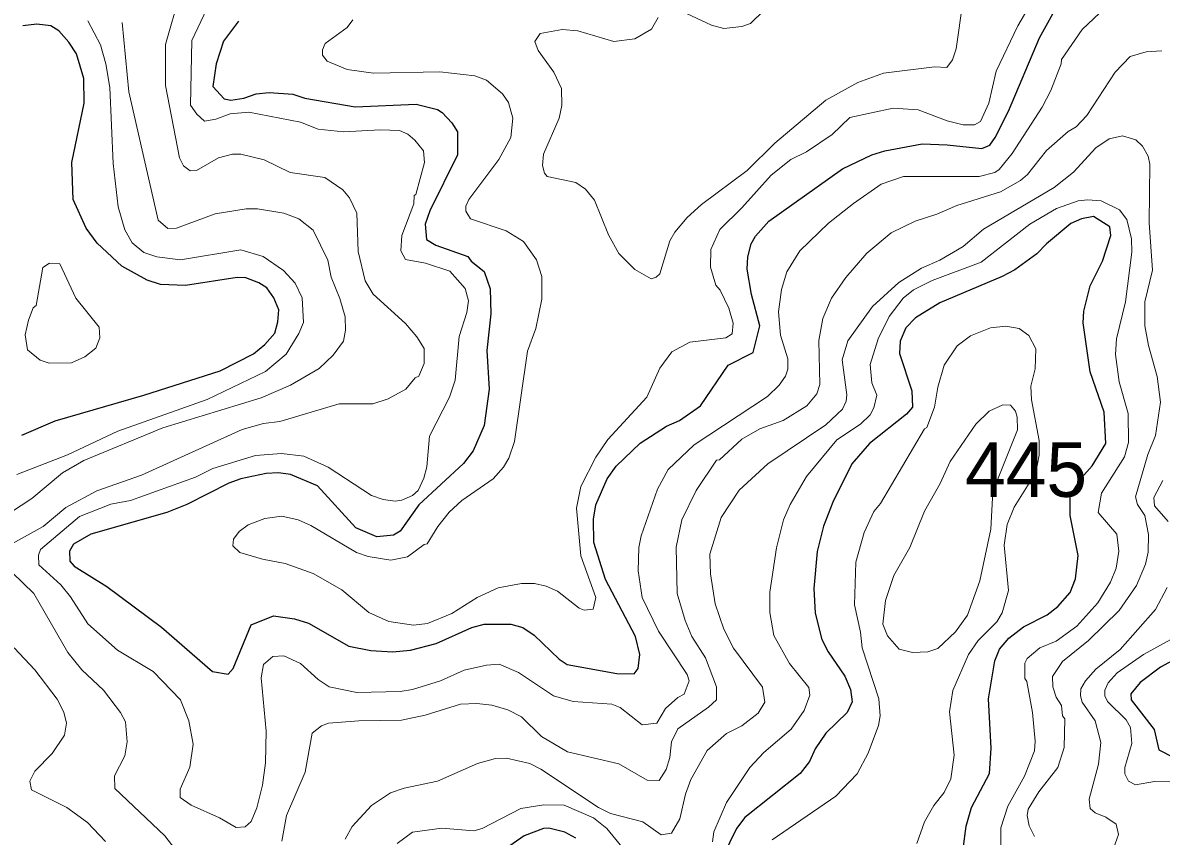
# Model space of a CAD drawing. Extents: x 673.3 to 698.5, y 6984.3 to 7012.3.
# Drawn here: x 691.793 to 693.46, y 6985.799 to 6986.991 of the extents above; entities that cross this region are included whole.
import ezdxf

# ---------------------------------------------------------------- set-up
doc = ezdxf.new("R2010")
doc.units = 0
doc.header["$LTSCALE"] = 0.032
doc.layers.add('1', color=7, linetype='Continuous', lineweight=25)
doc.layers.add('2', color=7, linetype='Continuous', lineweight=13)
doc.layers.add('21', color=7, linetype='Continuous')

msp = doc.modelspace()

# ---------------------------------------------------------------- linework, layer by layer
at = {"layer": '1'}
for points in [[(692.0041, 6986.2732), (691.8929, 6986.2414), (691.8675, 6986.2269), (691.8613, 6986.2167), (691.8618, 6986.202), (691.8684, 6986.1948), (691.9159, 6986.165), (691.9961, 6986.1051), (692.0708, 6986.0402), (692.0938, 6986.0366), (692.1013, 6986.0447), (692.1273, 6986.1088), (692.1603, 6986.122), (692.1909, 6986.1177), (692.2113, 6986.1114), (692.2706, 6986.0777), (692.3028, 6986.0709), (692.3343, 6986.0693), (692.3609, 6986.0718), (692.3983, 6986.0812), (692.4507, 6986.1049), (692.4688, 6986.1095), (692.5077, 6986.1098), (692.5253, 6986.105), (692.5417, 6986.0937), (692.5785, 6986.0586), (692.59, 6986.0505), (692.6627, 6986.0373), (692.6882, 6986.0369), (692.6942, 6986.0447), (692.6965, 6986.0652), (692.6903, 6986.0918), (692.6465, 6986.1751), (692.6291, 6986.2292), (692.6288, 6986.2633), (692.6323, 6986.2846), (692.6488, 6986.3227), (692.6622, 6986.3409), (692.6972, 6986.3747), (692.7355, 6986.3996), (692.7547, 6986.4081), (692.7856, 6986.4294), (692.8258, 6986.4889), (692.8628, 6986.5076), (692.8725, 6986.5469), (692.8603, 6986.5927), (692.8539, 6986.6299), (692.8546, 6986.6478), (692.8598, 6986.6666), (692.8659, 6986.678), (692.8853, 6986.6999), (692.9934, 6986.7768), (693.0364, 6986.797), (693.0553, 6986.8029), (693.11, 6986.8134), (693.1465, 6986.812), (693.1972, 6986.8063), (693.209, 6986.8113), (693.217, 6986.8225), (693.2363, 6986.8612), (693.2821, 6986.9687), (693.3119, 6987.0221)], [(692.1091, 6986.9927), (692.0868, 6986.9636), (692.0762, 6986.9302), (692.0713, 6986.8974), (692.0881, 6986.8789), (692.0978, 6986.8771), (692.1165, 6986.8802), (692.1348, 6986.8867), (692.154, 6986.8884), (692.1885, 6986.8859), (692.2061, 6986.8803), (692.2797, 6986.8672), (692.3692, 6986.8713), (692.4002, 6986.8635), (692.4073, 6986.8593), (692.4215, 6986.8442), (692.4295, 6986.831), (692.4294, 6986.7969), (692.389, 6986.7152), (692.3824, 6986.6958), (692.3843, 6986.6732), (692.3979, 6986.6648), (692.4447, 6986.6482), (692.4495, 6986.6413), (692.4685, 6986.6261), (692.4776, 6986.6009), (692.4785, 6986.5642), (692.4728, 6986.5105), (692.4759, 6986.454), (692.4687, 6986.4009), (692.4527, 6986.3638), (692.4382, 6986.345), (692.3731, 6986.2847), (692.3458, 6986.2461), (692.336, 6986.24), (692.3115, 6986.2378), (692.2805, 6986.2508), (692.2247, 6986.3124), (692.1852, 6986.3289), (692.1676, 6986.3313), (692.1494, 6986.3305), (692.1122, 6986.3225), (692.0947, 6986.3161), (692.0331, 6986.2848), (692.0041, 6986.2732)], [(691.7916, 6986.3866), (691.8402, 6986.4074), (691.9705, 6986.445), (692.0823, 6986.4809), (692.131, 6986.5057), (692.1475, 6986.5192), (692.1619, 6986.5361), (692.1666, 6986.5523), (692.168, 6986.5702), (692.1607, 6986.5878), (692.1503, 6986.6023), (692.1387, 6986.6098), (692.1197, 6986.6172), (692.1072, 6986.6173), (692.0313, 6986.6059), (691.9949, 6986.6074), (691.9754, 6986.6137), (691.9383, 6986.6339), (691.9021, 6986.6675), (691.8859, 6986.6895), (691.8668, 6986.7318), (691.865, 6986.7861), (691.8831, 6986.8726), (691.8822, 6986.9087), (691.8716, 6986.9449), (691.8604, 6986.9623), (691.8456, 6986.9787), (691.8342, 6986.9861), (691.8134, 6986.9886), (691.7929, 6986.9862)], [(693.1699, 6985.7808), (693.1746, 6985.8138), (693.1821, 6985.841), (693.2089, 6985.8909), (693.2113, 6985.928), (693.2073, 6986.0002), (693.2165, 6986.056), (693.2234, 6986.0729), (693.2372, 6986.0892), (693.2586, 6986.1057), (693.2933, 6986.1236), (693.3088, 6986.1357), (693.3269, 6986.1563), (693.3344, 6986.1761), (693.3383, 6986.2103), (693.3269, 6986.2689), (693.327, 6986.2979), (693.3428, 6986.3234), (693.3592, 6986.3418), (693.3792, 6986.3743), (693.3766, 6986.4201), (693.3562, 6986.4792), (693.3458, 6986.5511), (693.3468, 6986.5681), (693.3561, 6986.6051), (693.3741, 6986.6413), (693.3864, 6986.6791), (693.3849, 6986.6916), (693.3612, 6986.7066), (693.3435, 6986.7036), (693.3276, 6986.6964), (693.2919, 6986.6668), (693.2778, 6986.652), (693.2458, 6986.6288), (693.2273, 6986.6187), (693.1361, 6986.5804), (693.1004, 6986.5582), (693.086, 6986.5439), (693.0778, 6986.5243), (693.077, 6986.5061), (693.0948, 6986.4513), (693.0957, 6986.4277), (693.0873, 6986.4174), (693.0327, 6986.3743), (693.0073, 6986.3446), (692.9792, 6986.2882), (692.9657, 6986.253), (692.9564, 6986.2162), (692.9516, 6986.1619), (692.9532, 6986.1256)], [(692.9532, 6986.1256), (692.9633, 6986.0871), (692.9723, 6986.0693), (692.9967, 6986.0334), (693.0053, 6986.0142), (693.0074, 6985.996), (693.0002, 6985.9801), (692.9691, 6985.9499), (692.9534, 6985.9269), (692.945, 6985.9088), (692.9313, 6985.8911), (692.8502, 6985.8266), (692.8381, 6985.8106), (692.8179, 6985.7683)], [(693.5629, 6986.1032), (693.4592, 6986.0465), (693.4293, 6986.0241), (693.4158, 6986.0077), (693.4159, 6985.9989), (693.45, 6985.9556), (693.4567, 6985.9257), (693.4785, 6985.9145)], [(692.6027, 6985.7965), (692.5867, 6985.8052), (692.5632, 6985.8109), (692.5554, 6985.8106), (692.5272, 6985.7995), (692.4901, 6985.7737)]]:
    msp.add_lwpolyline(points, dxfattribs=at)
at = {"layer": '2'}
for points in [[(692.0231, 6987.0323), (692.0022, 6986.9587), (692.0021, 6986.8989), (692.0226, 6986.7925), (692.0284, 6986.7808), (692.0382, 6986.7736), (692.0476, 6986.7743), (692.0796, 6986.7926), (692.1003, 6986.7979), (692.1125, 6986.7979), (692.1464, 6986.7897), (692.1846, 6986.7713), (692.2351, 6986.7638), (692.2615, 6986.746), (692.2713, 6986.7343), (692.2821, 6986.7116), (692.284, 6986.6553), (692.2943, 6986.6126), (692.3061, 6986.5932), (692.3535, 6986.55), (692.3702, 6986.5307), (692.3806, 6986.5134), (692.381, 6986.4915), (692.373, 6986.4727), (692.3677, 6986.4705), (692.354, 6986.4538), (692.3283, 6986.4395), (692.3054, 6986.4323), (692.2561, 6986.4323), (692.1692, 6986.4063), (692.1455, 6986.4037), (692.1141, 6986.395), (691.967, 6986.3279), (691.9016, 6986.3051), (691.8563, 6986.2808), (691.8229, 6986.2529), (691.7781, 6986.2279)], [(692.6104, 6986.2098), (692.6038, 6986.2794), (692.6104, 6986.3112), (692.632, 6986.3544), (692.6499, 6986.3802), (692.7068, 6986.4424), (692.7258, 6986.4849), (692.7434, 6986.5084), (692.77, 6986.5227), (692.8224, 6986.5293), (692.8316, 6986.5349), (692.8334, 6986.5504), (692.8271, 6986.5727), (692.8142, 6986.5988), (692.808, 6986.6063), (692.7999, 6986.6328), (692.8005, 6986.6584), (692.8138, 6986.6877), (692.8462, 6986.7195), (692.8891, 6986.7672), (692.9179, 6986.7904), (692.9407, 6986.8016), (692.9784, 6986.827), (693.0039, 6986.8518), (693.0676, 6986.8656), (693.1044, 6986.863), (693.1465, 6986.847), (693.17, 6986.8412), (693.1866, 6986.8411), (693.1954, 6986.8458), (693.2079, 6986.8729), (693.2183, 6986.9199), (693.2501, 6986.9862), (693.2731, 6987.0258)], [(692.7651, 6987.0039), (692.8017, 6986.9869), (692.8195, 6986.9821), (692.8461, 6986.9851), (692.8588, 6986.9896), (692.8975, 6987.0282)], [(692.282, 6986.0097), (692.2419, 6986.0181), (692.2258, 6986.0285), (692.1998, 6986.052), (692.1754, 6986.0634), (692.1592, 6986.0625), (692.1456, 6986.0508), (692.1421, 6986.0311), (692.1493, 6985.9532), (692.1485, 6985.9064), (692.1443, 6985.874), (692.1357, 6985.8409), (692.1273, 6985.8208), (692.1185, 6985.8128), (692.1057, 6985.8117), (692.0813, 6985.8259), (692.0395, 6985.8448), (692.0233, 6985.8557), (692.0233, 6985.8681), (692.0377, 6985.9001), (692.0427, 6985.9338), (692.0363, 6985.9683), (692.0239, 6985.9991), (691.9839, 6986.0406), (691.9317, 6986.0717), (691.8881, 6986.1104), (691.8629, 6986.1495), (691.8485, 6986.1671), (691.8163, 6986.1964), (691.8161, 6986.2107), (691.819, 6986.2191), (691.8763, 6986.2676), (691.922, 6986.2854), (691.951, 6986.2907), (692.0458, 6986.3252), (692.0712, 6986.3378), (692.1337, 6986.3566), (692.1718, 6986.3599), (692.2047, 6986.3557), (692.2404, 6986.3396), (692.3035, 6986.2983), (692.3207, 6986.2922), (692.3381, 6986.2899), (692.3483, 6986.2915), (692.3638, 6986.2984), (692.3718, 6986.3054), (692.3804, 6986.3234), (692.3847, 6986.3401), (692.3888, 6986.3852), (692.4177, 6986.442), (692.4262, 6986.4671), (692.432, 6986.5312), (692.4433, 6986.566), (692.4459, 6986.5832), (692.4408, 6986.6012), (692.4184, 6986.6266), (692.3826, 6986.6383), (692.3534, 6986.644), (692.3468, 6986.6566), (692.3481, 6986.6791), (692.3656, 6986.7254), (692.366, 6986.7375), (692.3686, 6986.7392), (692.3813, 6986.786), (692.3797, 6986.8029), (692.3671, 6986.8188), (692.357, 6986.8273), (692.3448, 6986.8329), (692.3162, 6986.8339), (692.2627, 6986.8306), (692.2255, 6986.8348), (692.1999, 6986.8452), (692.1239, 6986.8598), (692.0967, 6986.8573), (692.0756, 6986.8492), (692.0592, 6986.8464), (692.0477, 6986.8565), (692.0387, 6986.8697), (692.0404, 6986.9645), (692.067, 6987.0201)], [(693.3873, 6987.0211), (693.3442, 6986.9806), (693.3141, 6986.9367), (693.3138, 6986.9305), (693.2985, 6986.8911), (693.2856, 6986.8667), (693.2419, 6986.7991), (693.2229, 6986.7754), (693.2165, 6986.7711), (693.1937, 6986.7655), (693.0829, 6986.7655), (693.0501, 6986.754), (693.0093, 6986.7259), (692.973, 6986.697), (692.9307, 6986.6566), (692.9118, 6986.6259), (692.904, 6986.6), (692.8995, 6986.5673), (692.9026, 6986.5328), (692.9132, 6986.4983), (692.9132, 6986.4831), (692.9099, 6986.473), (692.9009, 6986.4599), (692.8835, 6986.443), (692.776, 6986.3725), (692.7381, 6986.3362), (692.7225, 6986.3074), (692.6986, 6986.2391), (692.6951, 6986.222), (692.6941, 6986.1876), (692.6999, 6986.149), (692.7242, 6986.0995), (692.7657, 6986.036), (692.7689, 6986.0265), (692.7615, 6986.0071), (692.7524, 6986.0022), (692.7343, 6985.9862), (692.7213, 6985.9647), (692.7, 6985.9625), (692.6676, 6985.9875), (692.6557, 6985.9926), (692.5989, 6985.9966), (692.5702, 6986.0045), (692.5189, 6986.0391), (692.4904, 6986.0511), (692.4722, 6986.0496), (692.4396, 6986.0423), (692.4048, 6986.0266), (692.3639, 6986.0142), (692.3458, 6986.0113), (692.282, 6986.0097)], [(693.1698, 6987.0214), (693.16, 6986.9525), (693.1543, 6986.9365), (693.146, 6986.9252), (693.128, 6986.9258), (693.0536, 6986.9169), (693.0159, 6986.903), (692.9691, 6986.8773), (692.8943, 6986.814), (692.8536, 6986.7741), (692.7871, 6986.7244), (692.7658, 6986.7051), (692.7477, 6986.6839), (692.7405, 6986.6714), (692.7258, 6986.623), (692.7205, 6986.6178), (692.7132, 6986.6156), (692.6891, 6986.629), (692.6658, 6986.6528), (692.6508, 6986.6797), (692.6301, 6986.7307), (692.6169, 6986.7466), (692.6029, 6986.7564), (692.5608, 6986.7655), (692.5569, 6986.7703), (692.5542, 6986.7815), (692.5556, 6986.7979), (692.5787, 6986.8507), (692.5826, 6986.8694), (692.5818, 6986.8941), (692.5706, 6986.9183), (692.5478, 6986.95), (692.5429, 6986.9629), (692.5505, 6986.9749), (692.583, 6986.9805), (692.6057, 6986.9787), (692.6585, 6986.9631), (692.6892, 6986.9671), (692.7135, 6986.981), (692.7237, 6986.9985)], [(691.8881, 6986.9932), (691.907, 6986.9582), (691.9147, 6986.9305), (691.9205, 6986.8957), (691.9255, 6986.7843), (691.9328, 6986.7208), (691.9426, 6986.6872), (691.953, 6986.668), (691.9703, 6986.6542), (691.9891, 6986.6475), (692.024, 6986.6434), (692.1122, 6986.658), (692.1448, 6986.648), (692.1747, 6986.6279), (692.1917, 6986.6091), (692.2023, 6986.5878), (692.2039, 6986.5515), (692.1973, 6986.5355), (692.1789, 6986.5051), (692.1485, 6986.4796), (692.0628, 6986.4387), (691.9322, 6986.3922), (691.8584, 6986.3576), (691.7843, 6986.3287)], [(692.2763, 6986.995), (692.2681, 6986.9838), (692.2358, 6986.96), (692.2317, 6986.9511), (692.2318, 6986.9429), (692.2387, 6986.9344), (692.268, 6986.9222), (692.3065, 6986.9169), (692.4039, 6986.9186), (692.455, 6986.9129), (692.4719, 6986.9063), (692.4956, 6986.8865), (692.5043, 6986.8738), (692.5108, 6986.8507), (692.5077, 6986.8227), (692.4901, 6986.7903), (692.446, 6986.7315), (692.4418, 6986.7219), (692.4419, 6986.7144), (692.4486, 6986.7036), (692.5007, 6986.6858), (692.5262, 6986.6703), (692.5451, 6986.6432), (692.5533, 6986.6188), (692.5532, 6986.5856), (692.5444, 6986.5426), (692.5321, 6986.5094), (692.5132, 6986.3772), (692.5048, 6986.3526), (692.4971, 6986.3395), (692.4818, 6986.3226), (692.4361, 6986.2906), (692.4175, 6986.2736), (692.4009, 6986.2529), (692.3854, 6986.2272), (692.3809, 6986.2262), (692.3565, 6986.2085), (692.3319, 6986.2036), (692.2986, 6986.2089), (692.2816, 6986.2147), (692.2148, 6986.2542), (692.1961, 6986.2623), (692.1722, 6986.2678), (692.1475, 6986.2645), (692.1231, 6986.255), (692.11, 6986.2455), (692.1015, 6986.2344), (692.1007, 6986.2246), (692.1109, 6986.2146), (692.1442, 6986.2048), (692.1774, 6986.1985), (692.2181, 6986.1838), (692.2604, 6986.1602), (692.2999, 6986.1266), (692.3291, 6986.1137), (692.3654, 6986.1083), (692.3857, 6986.1107), (692.4212, 6986.1252), (692.4586, 6986.1488), (692.4894, 6986.1628), (692.5234, 6986.1692), (692.5422, 6986.1692), (692.5596, 6986.1653), (692.5761, 6986.1578), (692.6079, 6986.133), (692.6153, 6986.1302), (692.6285, 6986.1315), (692.6322, 6986.1489), (692.6104, 6986.2098)], [(691.7589, 6986.2629), (691.8064, 6986.294), (691.8513, 6986.3313), (691.8825, 6986.3494), (691.9979, 6986.3973), (692.1422, 6986.4412), (692.185, 6986.4599), (692.2272, 6986.484), (692.2476, 6986.5035), (692.2627, 6986.5244), (692.2658, 6986.5404), (692.2651, 6986.5599), (692.2572, 6986.5869), (692.2445, 6986.6178), (692.2399, 6986.6427), (692.2181, 6986.6867), (692.1971, 6986.7035), (692.1754, 6986.7116), (692.1366, 6986.7181), (692.1201, 6986.7182), (692.0747, 6986.7109), (692.0182, 6986.6895), (692.0054, 6986.6891), (691.9913, 6986.7014), (691.9482, 6986.8895), (691.9385, 6986.9908)], [(692.2409, 6985.9648), (692.2851, 6985.9681), (692.3478, 6985.9689), (692.3821, 6985.9762), (692.4342, 6985.9925), (692.4578, 6985.9933), (692.48, 6985.9909), (692.5034, 6985.9842), (692.5235, 6985.9742), (692.5528, 6985.9452), (692.5908, 6985.9226), (692.666, 6985.9053), (692.7075, 6985.8812), (692.7247, 6985.8805), (692.735, 6985.8967), (692.7405, 6985.9146), (692.7429, 6985.9374), (692.7522, 6985.9566), (692.7972, 6985.988), (692.8088, 6985.9991), (692.809, 6986.0178), (692.7926, 6986.0604), (692.7729, 6986.0918), (692.7631, 6986.115), (692.7512, 6986.1544), (692.7496, 6986.2224), (692.758, 6986.2627), (692.7793, 6986.3056), (692.8089, 6986.3498), (692.8134, 6986.3504), (692.8461, 6986.3805), (692.8725, 6986.3956), (692.9067, 6986.4079), (692.9413, 6986.4295), (692.9556, 6986.447), (692.9604, 6986.4609), (692.9589, 6986.5253), (692.9646, 6986.5572), (692.9772, 6986.5874), (692.9983, 6986.6175), (693.0289, 6986.6531), (693.0647, 6986.6831), (693.0996, 6986.6998), (693.1315, 6986.71), (693.1608, 6986.723), (693.2249, 6986.7429), (693.2539, 6986.7594), (693.2644, 6986.7681), (693.292, 6986.8037), (693.324, 6986.8315), (693.3356, 6986.8383), (693.351, 6986.8546), (693.3925, 6986.918), (693.4146, 6986.941), (693.438, 6986.9479), (693.4611, 6986.9494)], [(693.2748, 6985.7987), (693.2667, 6985.8145), (693.2636, 6985.8296), (693.2651, 6985.8386), (693.2807, 6985.8639), (693.3087, 6985.8999), (693.3179, 6985.9292), (693.3188, 6985.9711), (693.3156, 6985.9755), (693.3139, 6985.9907), (693.3061, 6986.0027), (693.3013, 6986.018), (693.301, 6986.0332), (693.3156, 6986.0552), (693.3534, 6986.0858), (693.3985, 6986.1299), (693.4238, 6986.1661), (693.4371, 6986.1976), (693.441, 6986.2152), (693.4417, 6986.2412), (693.4359, 6986.2689), (693.4254, 6986.2852), (693.4223, 6986.296), (693.4406, 6986.3582), (693.4516, 6986.3862), (693.4589, 6986.4348), (693.454, 6986.4725), (693.4413, 6986.5179), (693.4361, 6986.5465), (693.4361, 6986.5816), (693.4473, 6986.628), (693.4426, 6986.6977), (693.4436, 6986.7834), (693.4408, 6986.795), (693.4329, 6986.8099), (693.423, 6986.8191), (693.4035, 6986.8248), (693.3837, 6986.8205), (693.3644, 6986.8073)], [(693.3644, 6986.8073), (693.3315, 6986.7716), (693.3033, 6986.7493), (693.2, 6986.688), (693.1699, 6986.6627), (693.1359, 6986.6429), (693.109, 6986.6312), (693.0761, 6986.6099), (693.0375, 6986.5752), (693.0014, 6986.5246), (692.9931, 6986.4967), (692.9996, 6986.4458), (692.9987, 6986.4364), (692.9935, 6986.4247), (692.9692, 6986.4017), (692.8842, 6986.3445), (692.8421, 6986.3061), (692.8157, 6986.2657), (692.7993, 6986.2122), (692.7999, 6986.1833), (692.8071, 6986.1393), (692.8198, 6986.1024), (692.8336, 6986.0746), (692.8763, 6986.0173), (692.8798, 6985.9953), (692.8699, 6985.9795), (692.8459, 6985.961), (692.8233, 6985.9497), (692.7954, 6985.9248), (692.7713, 6985.882), (692.7636, 6985.8608), (692.7554, 6985.8246), (692.7429, 6985.8035), (692.7279, 6985.8012), (692.7012, 6985.82), (692.6535, 6985.8325), (692.6362, 6985.8412), (692.5515, 6985.8974), (692.5356, 6985.9056), (692.5012, 6985.9136), (692.4855, 6985.9128), (692.4591, 6985.9055), (692.4002, 6985.8798), (692.3516, 6985.8696), (692.3316, 6985.8629), (692.3036, 6985.844), (692.2754, 6985.8132), (692.2652, 6985.795)], [(692.8032, 6985.7908), (692.805, 6985.8054), (692.8236, 6985.8484), (692.8578, 6985.8998), (692.878, 6985.9215), (692.9181, 6985.956), (692.9375, 6985.9834), (692.9456, 6986.0058), (692.9443, 6986.0168), (692.9157, 6986.052), (692.8927, 6986.0933), (692.8872, 6986.1267), (692.8872, 6986.1568), (692.8969, 6986.2214), (692.907, 6986.2627), (692.9167, 6986.2852), (692.9405, 6986.3262), (692.9852, 6986.3795), (693.0197, 6986.4025), (693.0341, 6986.4164), (693.0394, 6986.4266), (693.0435, 6986.4453), (693.0364, 6986.4634), (693.0338, 6986.4901), (693.0458, 6986.5277), (693.0616, 6986.5605), (693.0824, 6986.5874), (693.0973, 6986.5992), (693.1249, 6986.613), (693.1967, 6986.6401), (693.2675, 6986.6955), (693.3069, 6986.7187), (693.3387, 6986.7296), (693.3524, 6986.7313), (693.3724, 6986.7296), (693.399, 6986.7168), (693.41, 6986.7025), (693.4165, 6986.6742), (693.4173, 6986.6544), (693.4076, 6986.5816), (693.3945, 6986.5274), (693.393, 6986.5047), (693.3985, 6986.4647), (693.4117, 6986.4183), (693.4124, 6986.3759), (693.4066, 6986.3547), (693.3727, 6986.3015), (693.368, 6986.2732), (693.3953, 6986.2417), (693.3979, 6986.2165), (693.3943, 6986.1915), (693.3857, 6986.1712), (693.3675, 6986.141), (693.3368, 6986.1067), (693.3061, 6986.0847), (693.2824, 6986.0748), (693.2638, 6986.0596), (693.2602, 6986.0525)], [(693.1022, 6985.7884), (693.1133, 6985.8201), (693.127, 6985.8441), (693.1421, 6985.8632), (693.152, 6985.8832), (693.1567, 6985.9179), (693.1503, 6985.9813), (693.1551, 6986.0127), (693.1781, 6986.0651), (693.1922, 6986.0857), (693.2193, 6986.1129), (693.2274, 6986.1264), (693.2365, 6986.1589), (693.2301, 6986.2253), (693.2345, 6986.2555), (693.2449, 6986.2809), (693.2763, 6986.3319), (693.2816, 6986.3574), (693.2816, 6986.3785), (693.2701, 6986.4384), (693.2692, 6986.4581), (693.2757, 6986.4839), (693.2763, 6986.5131), (693.2665, 6986.5327), (693.2521, 6986.5429), (693.2327, 6986.5463), (693.2099, 6986.5439), (693.181, 6986.5319), (693.1613, 6986.5175), (693.1422, 6986.489), (693.1329, 6986.4566), (693.1281, 6986.4276), (693.1168, 6986.3977), (693.1133, 6986.396), (693.0492, 6986.2866), (693.0391, 6986.2746), (693.0251, 6986.2441), (693.0127, 6986.2005), (693.011, 6986.1381), (693.0198, 6986.0982), (693.0223, 6986.0748), (693.0467, 6986.0005), (693.0485, 6985.9753), (693.046, 6985.9612), (693.0308, 6985.9207), (693.0148, 6985.8906), (692.9836, 6985.8578), (692.8905, 6985.7938)], [(693.4623, 6986.3202), (693.4492, 6986.2952), (693.4502, 6986.2831), (693.4704, 6986.2603)], [(691.7773, 6986.1854), (691.8091, 6986.1544), (691.8588, 6986.0681), (691.8793, 6986.0427), (691.9112, 6986.0132), (691.936, 6985.9803), (691.9433, 6985.9665), (691.9457, 6985.9374), (691.9425, 6985.9168), (691.9271, 6985.8875), (691.9277, 6985.8692), (692.0008, 6985.7998), (692.0288, 6985.7637)], [(693.4689, 6986.1634), (693.4519, 6986.1313), (693.3998, 6986.0727), (693.3642, 6986.0436), (693.3491, 6986.0269), (693.3423, 6986.0152), (693.3417, 6986.0049), (693.3446, 6985.9956), (693.3635, 6985.9683), (693.3717, 6985.9364), (693.3683, 6985.9048), (693.3547, 6985.8536), (693.3563, 6985.8396), (693.3632, 6985.8335), (693.3791, 6985.8272), (693.3941, 6985.8169), (693.3976, 6985.8015)], [(693.3775, 6986.0129), (693.3826, 6986.0239), (693.3956, 6986.0383), (693.4341, 6986.0654), (693.499, 6986.1008)], [(691.8569, 6985.9646), (691.8532, 6985.981), (691.8433, 6985.9997), (691.8107, 6986.0428), (691.7805, 6986.0749)], [(693.2602, 6986.0525), (693.2602, 6986.0301), (693.2634, 6986.0256), (693.2715, 6985.9803), (693.2756, 6985.9383), (693.2747, 6985.9244), (693.26, 6985.8873), (693.2356, 6985.8432), (693.2252, 6985.8112), (693.2251, 6985.7599)], [(693.4948, 6985.8785), (693.4501, 6985.8793), (693.4225, 6985.8745), (693.4123, 6985.8797), (693.4069, 6985.8906), (693.4068, 6985.8999), (693.4172, 6985.9348), (693.4151, 6985.9586), (693.409, 6985.9698), (693.3817, 6985.9964), (693.3775, 6986.0049), (693.3775, 6986.0129)], [(691.9142, 6985.7912), (691.8877, 6985.8193), (691.8573, 6985.8414), (691.8056, 6985.8669), (691.8035, 6985.8797), (691.8107, 6985.8944), (691.8359, 6985.9204), (691.8542, 6985.9472), (691.8569, 6985.9646)], [(692.1725, 6985.792), (692.1792, 6985.8294), (692.2065, 6985.893), (692.217, 6985.9502), (692.2306, 6985.9606), (692.2409, 6985.9648)], [(692.3412, 6985.7886), (692.3639, 6985.8052), (692.4067, 6985.811), (692.4537, 6985.8068), (692.4659, 6985.8104), (692.5226, 6985.8395), (692.556, 6985.8451), (692.5859, 6985.8445), (692.6288, 6985.826), (692.6482, 6985.8104), (692.6702, 6985.7838)], [(693.3976, 6985.8015), (693.3877, 6985.7745)]]:
    msp.add_lwpolyline(points, dxfattribs=at)
for points in [[(691.8708, 6986.587), (691.8471, 6986.6373), (691.832, 6986.6383), (691.8224, 6986.632), (691.8124, 6986.5763), (691.8081, 6986.573), (691.8012, 6986.5552), (691.7967, 6986.5334), (691.7999, 6986.5116), (691.8187, 6986.4962), (691.8319, 6986.4918), (691.8643, 6986.4926), (691.8837, 6986.5014), (691.9001, 6986.5141), (691.9058, 6986.5293), (691.905, 6986.5445)], [(693.096, 6986.0683), (693.1182, 6986.0691), (693.133, 6986.0742), (693.1588, 6986.0987), (693.1766, 6986.1227), (693.1947, 6986.1731), (693.2105, 6986.2489), (693.2136, 6986.3039), (693.2497, 6986.3944), (693.2493, 6986.4129), (693.2467, 6986.4219), (693.2394, 6986.4306), (693.2284, 6986.431), (693.2084, 6986.4215), (693.1889, 6986.4028), (693.1509, 6986.3482), (693.1364, 6986.3157), (693.1137, 6986.2754), (693.0919, 6986.2219), (693.0685, 6986.1811), (693.0564, 6986.1442), (693.0526, 6986.1099), (693.0592, 6986.0925), (693.0763, 6986.0732)]]:
    msp.add_lwpolyline(points, close=True, dxfattribs=at)

# ---------------------------------------------------------------- texts
at = {"layer": '21'}
msp.add_text('445', height=0.08, dxfattribs=at).set_placement((693.173, 6986.2962))

doc.saveas('drawing.dxf')
